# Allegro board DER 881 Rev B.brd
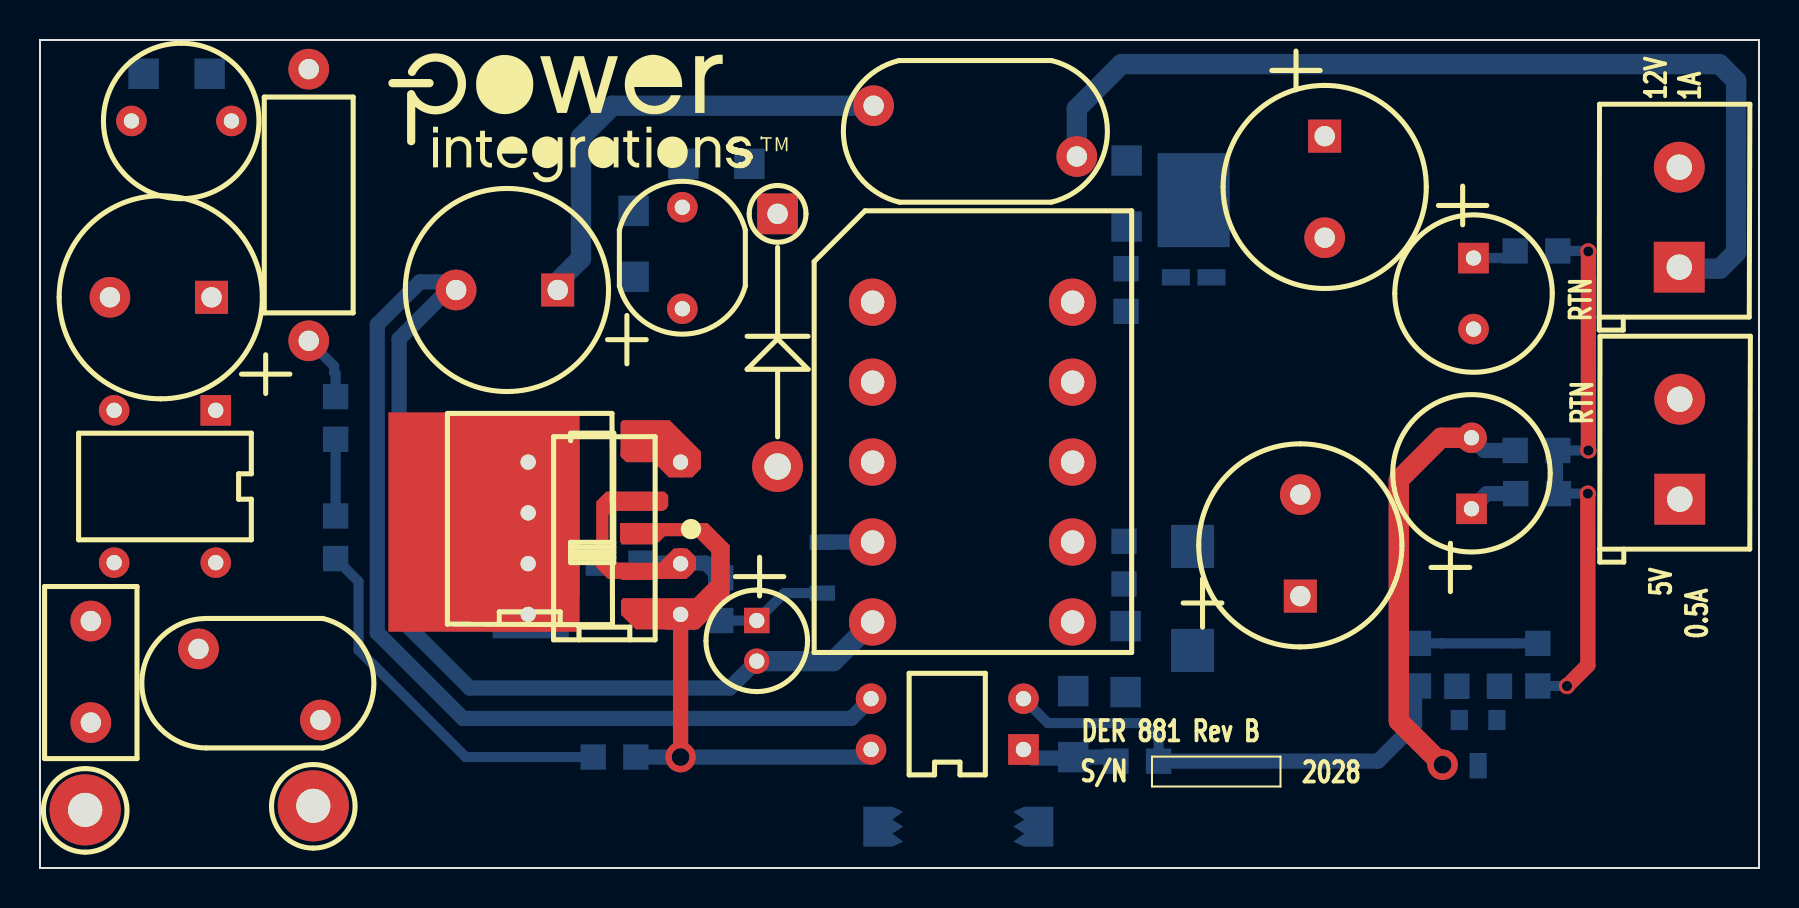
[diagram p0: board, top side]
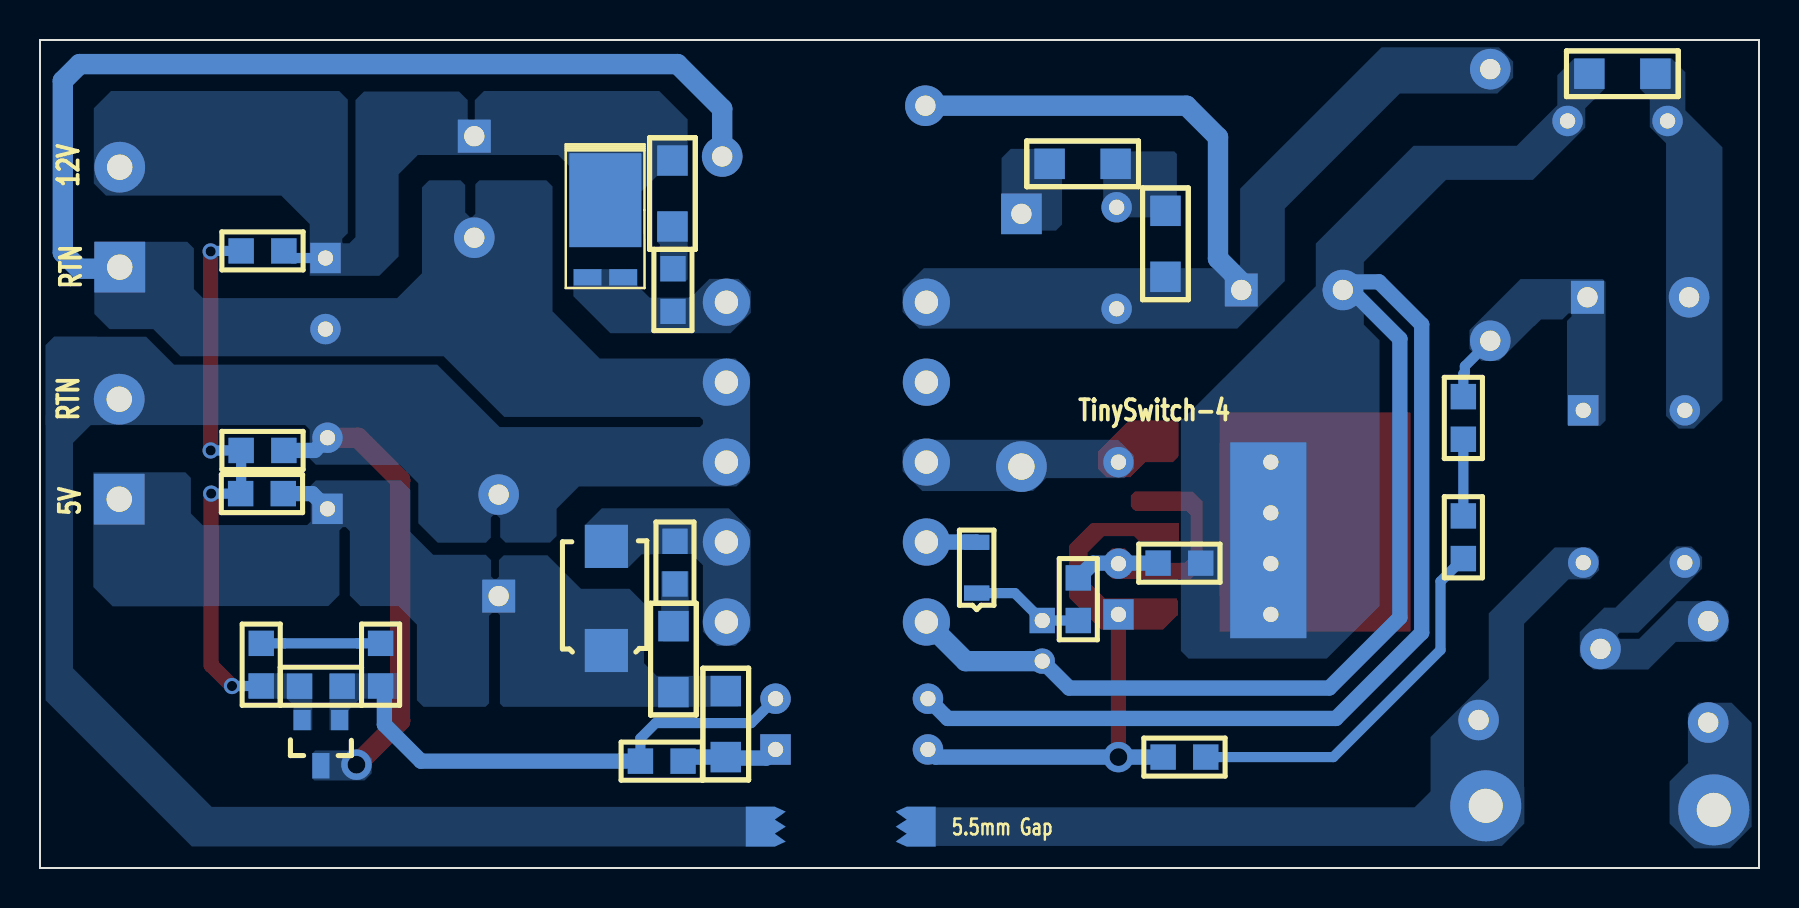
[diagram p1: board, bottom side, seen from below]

Outline 85.95 x 41.43 mm; copper layers: TOP, BOTTOM. Coordinates in mm from the lower left corner of the outline.
Outline path: 0,41.43 0,0 85.95,0 85.95,41.43 0,41.43

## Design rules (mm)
constraint set DEFAULT: min track width 0.508

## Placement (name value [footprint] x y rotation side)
BR1  DF10M  [PI_4-EDIP]  8.79 22.9 180 top
C1  18 uF  [PIPOLCAPCYLD400LS200040]  8.58 28.55 180 top
C2  18 uF  [PIPOLCAPCYLD400LS200040]  25.89 28.92 180 top
C3  1 nF  [PI_NP_CAP300X250LS200D030]  32.12 27.98 90 top
C4  0.1 uF  [PISMC0805]  30.05 15.25 180 bottom
C5  10 uF  [PIPOLCAPCLYD200LS80030]  35.84 12.38 270 top
C6  1 nF  [PINPYCAPRAD540X290LS400040]  41.68 38.14 0 top
C7  220 pF  [PISMC0805]  54.31 27.85 90 bottom
C8  1 nF  [PISMC0805]  54.2 16.35 270 bottom
C9  220 nF  [PISMC0805]  68.92 9.11 90 bottom
C10  1200 uF  [PIPOLCAPCYLD400LS200040]  63.02 13.6 90 top
C11  470  uF  [PIPOLCAPCLYD320LS140030]  71.58 17.97 90 top
C12  1000 uF  [PIPOLCAPCYLD400LS200040]  64.24 36.61 270 top
C13  680 uF  [PIPOLCAPCLYD320LS140030]  71.68 30.52 270 top
C15  1 uF  [PISMC0805]  70.84 9.09 0 bottom
D1  1N4007GP  [PIDV200X110X040DO41]  36.88 30.95 270 top
D2  BAV19WS  [PISMSOD323]  39.12 13.75 90 bottom
D3  PDS5100-13  [PISMDPOWERDI5]  58.57 29.55 180 bottom
D4  B280-13-F  [PISMSMB]  57.63 10.88 90 bottom
F1  1.25 A  [PI_RST_MICROFUSE]  2.54 7.28 90 top
J1  TERMINAL BLOCK  [PI_TERM_BLOCK_2PIN_LS200]  81.97 30.06 0 top
J2  TERMINAL BLOCK  [PI_TERM_BLOCK_2PIN_LS200]  81.99 18.45 0 top
L  WHT  [PITPKEYSTONE125X125]  2.26 2.91 0 top
L1  1000 uH  [PICHOKETOKINVD345H453LS197D030]  4.57 37.38 0 top
L2  Ferrite Bead (3.5 x 4.45 mm)  [PI12WRESD180LS675D040]  13.44 24.6 90 top
N  BLK  [PITPKEYSTONE125X125]  13.67 3.11 0 top
NOREF  -  []  -231.65 -152.08 0 top
NOREF#2  -  []  -153.83 46.93 0 top
NOREF#3  -  []  85.95 41.43 270 top
NOREF#4  -  []  0 41.43 0 top
NOREF#5  -  []  17.42 40.73 0 top
R1  1.3 M  [PISMR0805]  14.78 23.58 270 bottom
R2  1.3 M  [PISMR0805]  14.78 17.62 270 bottom
R3  1.3 M  [PISMR0805]  27.66 5.55 0 bottom
R4  332 k  [PISMR1206]  29.68 29.58 90 bottom
R5  100  [PISMR1206]  32.17 35.23 0 bottom
R6  9.1 k  [PISMR0805]  34.04 14.52 270 bottom
R8  51  [PISMR1206]  54.33 32.09 90 bottom
R9  10  [PISMR1206]  54.28 12.1 270 bottom
R10  1.00 k  [PISMR0805]  53.8 5.35 0 bottom
R11  3.30 k  [PISMR0805]  74.89 9.11 90 bottom
R12  100  [PISMR1206]  51.66 5.55 90 bottom
R13  33.2 k  [PISMR0805]  73.79 18.73 0 bottom
R14  54.9 k  [PISMR0805]  73.76 30.87 0 bottom
R15  10 k  [PISMR0805]  75.9 20.89 180 bottom
R17  10 k  [PISMR1206]  5.18 39.74 0 bottom
RV1A  300 Vac  [PIDISC350X225LS240X140040]  7.92 10.96 0 top
SG1  5.5mm gap  [PI_SPARK_GAP_5P5MM]  45.91 2.07 0 bottom
T1  EE19  [PI_BOBBIN_EE19_TF-1932_10P]  41.63 28.31 0 top
U1  TNY289PG  [PIICDIP8CSHORT5678]  32.03 12.69 90 top
U2  PS2501-1-H-A  [PI_DIP4]  49.17 5.93 90 top
U3  TL431CDBZR  [PISMSOT23123_1]  72.85 7.4 0 bottom
U4A  TNY289KG  [PI_SMD_ESOP_11-12P_SHORT7-11]  29.92 13.02 90 top
U5A  TNY288DG*  [PISMSO8DNSHORT5678]  30.21 16.93 90 top

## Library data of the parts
BR1 = DIODE BRIDGE_+-~~
C1 C2 = CAP POL: alternate symbols: (pipolcapclyd395x630ls200030h)
C3 C4 C7 C9 C15 = CAP NP
C5 = CAP POL: alternate symbols: (pipolcapclyd200ls80030h)
C6 = CAP NP: alternate symbols: (pinpycaprad540x290ls400040h,pinpycaprad500x220ls400040)
C8 = CAP NP: alternate symbols: (pismc0805_1)
C10 C12 = CAP POL: alternate symbols: (pipolcapcyld400ls200040800h)
C11 = CAP POL: alternate symbols: (pipolcapclyd320ls140030430h)
C13 = CAP POL: alternate symbols: (pipolcapclyd320ls140d30h750)
D1 = DIODE: alternate symbols: (pidax475x125040do41,pidv200x110x040do41wbead,pidax390x125040do41)
D2 = DIODE
D3 = DIODE SCHOTTKY_PWRDI_AAC
D4 = DIODE SCHOTTKY
F1 = FUSE: alternate symbols: (pirstmicrofusehoz)
J1 J2 = CON2
L N = TESTPOINT
L1 = INDUCTOR
L2 = INDUCTOR: alternate symbols: (pi12wvresd180ls150d040,pi12wvresd180ls200d040,pi12wvresd180ls250d040)
R1-R6 R8-R15 R17 = R
RV1A = VARISTOR
SG1 = SPARK_GAP
T1 = BEE19_10P/GENERIC
U1 U5A = TNY_3
U2 = OPTO_DIP
U3 = TL431CDBZR
U4A = DEV_TNY_3_eSOP

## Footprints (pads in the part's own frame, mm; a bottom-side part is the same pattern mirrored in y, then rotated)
PI12WRESD180LS675D040
  round 2.032 hole 1.016: 1(1.778,0) 2(15.367,0)
PI_4-EDIP
  rect 1.524x1.524 hole 0.762: 1(0,0)
  round 1.524 hole 0.762: 2(5.08,0) 3(5.08,7.62) 4(0,7.62)
PI_BOBBIN_EE19_TF-1932_10P
  round 2.362 hole 1.168: 1(0,0) 2(0,-4) 3(0,-8.001) 4(0,-11.999) 5(0,-16) 6(10,-16) 7(10,-11.999) 8(10,-8.001) 9(10,-4) 10(10,0)
PI_DIP4
  rect 1.524x1.524 hole 0.762: 1(0,0)
  round 1.524 hole 0.762: 2(2.54,0) 3(2.54,7.62) 4(0,7.62)
PI_NP_CAP300X250LS200D030
  round 1.524 hole 0.762: 1(0,0) 2(5.08,0)
PI_RST_MICROFUSE
  round 2.032 hole 1.016: 1(0,0) 2(5.08,0)
PI_SMD_ESOP_11-12P_SHORT7-11
  rect 0.762x1.727 smd: 1(0,0) 2(1.778,0) 3(3.556,0) 4(5.334,0) 6(8.89,0) 7(8.89,10.897) 8(7.112,10.897) 9(5.334,10.897) 10(3.556,10.897) 11(1.778,10.897) 12(0,10.897)
PI_SPARK_GAP_5P5MM
  custom 0.5x0.5 smd: 1(-3.75,0) 2(3.75,0)
PI_TERM_BLOCK_2PIN_LS200
  rect 2.54x2.54 hole 1.27: 1(0,0)
  round 2.54 hole 1.27: 2(0,5.001)
PICHOKETOKINVD345H453LS197D030
  round 1.524 hole 0.762: 1(0,0) 2(5,0)
PIDISC350X225LS240X140040
  round 2.032 hole 1.016: 1(0,0) 2(6.096,-3.556)
PIDV200X110X040DO41
  rect 2.032x2.032 hole 1.016: 1(-1.778,0)
  round 2.54 hole 1.321: 2(10.865,0)
PIICDIP8CSHORT5678
  rect 1.524x1.524 hole 0.762: 1(0,0)
  round 1.524 hole 0.762: 2(2.54,0) 4(7.62,0) 5(7.62,7.62) 6(5.08,7.62) 7(2.54,7.62) 8(0,7.62)
PINPYCAPRAD540X290LS400040
  round 2.032 hole 1.016: 1(0,0) 2(10.16,-2.54)
PIPOLCAPCLYD200LS80030
  rect 1.27x1.27 hole 0.762: 1(0,0)
  round 1.27 hole 0.762: 2(2.032,0)
PIPOLCAPCLYD320LS140030
  rect 1.524x1.524 hole 0.762: 1(0,0)
  round 1.524 hole 0.762: 2(3.556,0)
PIPOLCAPCYLD400LS200040
  rect 1.651x1.651 hole 1.016: 1(0,0)
  round 2.032 hole 1.016: 2(5.08,0)
PISMC0805
  rect 1.27x1.27 smd: 1(0,0) 2(2.134,0)
PISMDPOWERDI5
  rect 1.397x0.813 smd: 1(0,0) 3(1.778,0)
  rect 3.607x4.699 smd: 2(0.889,3.861)
PISMR0805
  rect 1.27x1.27 smd: 1(0,0) 2(2.134,0)
PISMR1206
  rect 1.524x1.524 smd: 1(0,0) 2(3.302,0)
PISMSMB
  rect 2.159x2.159 smd: 1(0,0) 2(5.207,0)
PISMSO8DNSHORT5678
  rect 0.635x2.388 smd: 1(0,0)
  oval 0.635x2.388 smd: 2(1.27,0) 4(3.81,0) 5(3.81,4.978) 6(2.54,4.978) 7(1.27,4.978) 8(0,4.978)
PISMSOD323
  rect 0.762x1.27 smd: 1(0,0) 2(2.54,0)
PISMSOT23123_1
  rect 0.864x1.016 smd: 1(-1.88,0) 2(0,0)
  rect 0.864x1.27 smd: 3(-0.94,2.286)
PITPKEYSTONE125X125
  round 3.556 hole 1.702: 1(0,0)

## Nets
BP: C4.1 R6.1 U1.2 U4A.2 U5A.2
D: D1.2 T1.3 U1.4 U4A.6 U5A.4
EN: R3.2 U1.1 U2.4 U4A.1 U5A.1
NC3: U4A.3
NC4: U4A.4
S: C2.2 C4.2 C5.2 L1.2 R17.2 T1.5 U1.5(S) U2.3(E) U4A.7(S7) U5A.5(S)
SOURCE: U1.6 U1.7 U1.8 U4A.8 U4A.9 U4A.10 U4A.11 U4A.12 U5A.6 U5A.7 U5A.8
N12047772: F1.1 L.1
N12047776: BR1.3 F1.2 RV1A.1
N12047800: C2.1 C3.1 C6.1 L2.2 R4.1 T1.1
N12047808: C6.2 C10.2 C11.2 C12.2 C13.2 J1.1 J2.2 R15.2 SG1.2 T1.8 T1.9 U3.3
N12047874: C7.1 D3.1 D3.3 T1.10
N12047882: C7.2 R8.1
N12047886: C12.1 C13.1 D3.2 J1.2 R8.2 R14.1
N12047956: BR1.2 C1.2 L1.1 R17.1
N12047964: BR1.1 C1.1 L2.1 R1.1
N12048106: BR1.4 N.1 RV1A.2 SG1.1
N12048278: R1.2 R2.1
N12048330: C3.2 R4.2 R5.1
N12048338: D1.1 R5.2
N12048416: D2.2 T1.4
N12048424: C8.1 D4.2 T1.6 T1.7
N12048440: C10.1 C11.1 D4.1 J2.1 R9.2 R12.2 R13.1
N12048540: R2.2 R3.1
N12048564: C8.2 R9.1
N12048682: C5.1 D2.1 R6.2
N12048994: R10.1 R12.1 U2.1
N12049130: C9.1 C15.1 R10.2 U2.2 U3.1
N12049134: C15.2 R11.1 R13.2 R14.2 R15.1 U3.2(VREF)
N12051927: C9.2 R11.2

Pads without a net: T1 2

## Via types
v1: diameter 0.813, hole 0.508, TOP to BOTTOM, 4 vias
v2: diameter 1.524, hole 0.889, TOP to BOTTOM, 2 vias

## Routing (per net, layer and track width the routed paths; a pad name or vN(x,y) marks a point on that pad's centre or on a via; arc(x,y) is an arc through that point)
BP: length 4.3
  BOTTOM w0.762: R6.1 33.3,15.25 32.05,15.25 U1.2 32,15.25 C4.1
EN: length 19.1
  TOP w0.762: U1.1 v2(32.03,5.55)
  BOTTOM w0.762: U2.4 41.17,5.55 v2(32.03,5.55) R3.2
S: length 91.6
  BOTTOM w0.762: U2.3 40.57,7.48 21.16,7.48 16.87,11.77 16.87,27.19 19,29.33 20.81,29.33 17.96,26.48 17.96,12.54 21.49,9 34.49,9 C5.2
  BOTTOM w1.016: T1.5 39.67,10.35 C5.2
N12047800: length 23
  BOTTOM w1.016: C6.1 28.63,38.14 27.05,36.56 27.05,30.49 25.89,29.33
N12047808: length 70.5
  TOP w1.016: C11.2 70.05,21.53 67.94,19.42 67.94,7.35 v2(70.13,5.17)
  BOTTOM w0.762: C11.2 72.21,20.89 R15.2
  BOTTOM w1.016: C6.2 51.84,37.99 54.08,40.22 83.97,40.22 84.81,39.38 84.81,30.8 84,29.99 82.04,29.99 J1.1
N12047886: length 2.2
  BOTTOM w0.508: C13.1 73.41,30.52 R14.1
N12047964: length 3.4
  BOTTOM w0.508: R1.1 14.78,24.73 14.71,24.8 14.71,25.11 L2.1
N12048278: length 3.8
  BOTTOM w0.508: R1.2 R2.1
N12048416: length 2.5
  BOTTOM w0.762: D2.2 39.13,16.31 T1.4
N12048440: length 2.5
  BOTTOM w0.762: R13.1 72.34,18.73 C11.1
N12048540: length 19
  BOTTOM w0.508: R3.1 21.29,5.55 15.93,10.91 15.93,14.34 R2.2
N12048682: length 5.6
  BOTTOM w0.508: R6.2 C5.1 37.21,13.75 D2.1
N12048994: length 4.9
  BOTTOM w0.762: U2.1 49.2,5.93 49.63,5.5 51.61,5.5 R12.1 53.59,5.55 R10.1
N12049130: length 24.2
  BOTTOM w0.508: U2.2 50.39,7.25 55.17,7.25 55.93,6.49 R10.2
  BOTTOM w0.762: R10.2 66.9,5.35 68.73,7.18 68.73,9.11
N12049134: length 28.2
  TOP w0.762: v1(77.39,18.73) 77.39,10.15 v1(76.35,9.11) ; v1(77.42,30.85) v1(77.42,20.89)
  BOTTOM w0.508: v1(77.39,18.73) R13.2 75.9,18.76 R15.1 v1(77.42,20.89) ; v1(77.42,30.85) 77.39,30.87 R14.2 ; 74.9,9.11 v1(76.35,9.11)
N12051927: length 6
  BOTTOM w0.508: C9.2 70.07,11.24 R11.2

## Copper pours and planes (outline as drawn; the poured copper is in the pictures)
BP on TOP (solid shape): 31.41,18.64 31.41,18.1 31.18,17.87 28.63,17.87 28.42,17.67 28.42,15.56 28.7,15.28 30.99,15.28 31.7,15.99 32.36,15.99 32.8,15.55 32.8,14.95 32.32,14.47 28.4,14.47 27.81,15.05 27.81,18.33 28.32,18.83 31.22,18.83
D on TOP (solid shape): 33.05,20.84 33.05,19.98 32.61,19.55 31.45,19.55 30.68,20.31 29.31,20.31 29.03,20.59 29.03,22.29 29.15,22.4 31.48,22.4
D on BOTTOM: 42.82,19.85 42.82,20.89 42.29,21.43 32.05,21.43 31.27,20.64 31.27,19.98 31.74,19.51 35.65,19.51 36.3,18.86 41.83,18.86
EN on TOP (solid shape): 34.49,16.14 34.49,13.53 32.91,11.94 29.78,11.94 29.11,12.61 29.11,13.5 32.72,13.5 33.57,14.35 33.57,15.8 32.77,16.6 31.24,16.6 30.94,16.29 29.01,16.29 29.01,17.26 33.38,17.26
S on TOP (solid shape): 26.97,11.82 17.42,11.82 17.42,22.8 26.97,22.8
S on BOTTOM (solid shape): 26.44,11.49 22.63,11.49 22.63,21.3 26.44,21.3
S on BOTTOM: 21.62,10.48 18.97,13.12 18.97,26.4 19.76,27.19 19.76,30.32 15.65,34.43 11.3,34.43 8.69,37.05 8.69,38.01 7.72,38.98 7.72,40.5 9.25,40.5 10.08,39.66 10.08,38.16 12.12,36.13 17.27,36.13 22.16,31.24 22.16,29.11 28.8,22.47 28.91,22.47 28.91,10.86 28.52,10.48
SOURCE on TOP (solid shape): 26.81,16.4 23.51,16.4 23.51,21.22 26.81,21.22
SOURCE on TOP (solid shape): 22.12,14.42 18.16,14.42 18.16,22.29 22.12,22.29
SOURCE on TOP (solid shape): 26.97,13.65 21.95,13.65 21.95,21.25 26.97,21.25
N12047772 on BOTTOM: 3.53,5.27 3.56,5.3 3.56,7.73 3.02,8.27 1.37,8.27 0.37,7.26 0.37,2.07 1.45,0.98 3.23,0.98 4.47,2.23 4.47,4.33
N12047776 on BOTTOM: 2.11,11.32 4.15,11.32 5.54,9.93 8.29,9.93 8.97,10.61 8.97,11.8 7.73,13.03 7.18,13.03 4.11,16.09 3.38,16.09 2.84,15.56 2.84,14.97 6.05,11.77 6.96,11.77 7.06,11.67 7.06,11.57 6.96,11.47 5.99,11.47 4.11,13.35 2.03,13.35 1.52,12.84 1.52,11.9
N12047800 on BOTTOM: 42.82,28.94 42.82,27.83 41.99,26.99 26.09,26.99 23.71,29.36 23.71,33 17.96,38.75 13.08,38.75 12.29,39.54 12.29,40.35 13,41.06 18.87,41.06 25.95,33.99 25.95,30.2 26.14,30.01 41.76,30.01
N12047808 on BOTTOM: 72.16,20.18 67.97,20.18 67.04,19.25 67.04,17.25 66.07,16.28 63.66,16.28 63.41,16.52 63.41,17.53 63.27,17.67 63.12,17.67 62.94,17.49 62.94,16.55 62.67,16.28 60.45,16.28 60.12,16.61 60.12,17.97 59,19.09 51.13,19.09 50.44,19.77 50.44,24.75 51.18,25.49 57.96,25.49 60.32,27.85 60.32,34.1 60.63,34.4 63.98,34.4 64.19,34.2 64.19,32.73 64.34,32.58 64.47,32.58 64.69,32.8 64.69,34.18 64.92,34.4 66.5,34.4 66.85,34.05 66.85,29.76 68.1,28.51 77.8,28.51 78.26,28.97 78.26,31 78.59,31.33 83.21,31.33 83.21,30.14 83.24,30.11 83.24,27.72 82.47,26.96 80.29,26.96 78.93,25.6 65.77,25.6 62.74,22.57 52.96,22.57 52.81,22.42 52.81,22.21 52.96,22.06 62.97,22.06 66.09,25.18 79.25,25.18 80.64,26.58 85.24,26.58 85.66,26.16 85.66,22.66 85.67,22.64 85.67,22.16 72.69,22.16 72.47,21.93 72.47,20.49
N12047808 on BOTTOM: 72.19,5.88 72.34,5.73 72.34,4.48 72.24,4.38 69.72,4.38 69.37,4.74 69.37,5.47 69.77,5.88
N12047808 on BOTTOM: 85.24,26.58 83.11,26.58 82.83,26.3 82.83,22.16 83.41,22.16 84.3,21.27 84.3,10 77.37,3.06 49.63,3.06 49.63,1.08 78.36,1.08 85.67,8.4 85.67,26.15
N12047874 on BOTTOM: 51.42,26.76 57.44,26.76 59.28,28.61 59.28,29.96 56.08,29.96 56.08,29.15 55.47,28.54 53.42,28.54 52.48,29.48 51.03,29.48 50.41,28.85 50.41,27.78
N12047882 on BOTTOM: 53.67,29.35 54.94,29.35 54.95,29.36 54.95,31.19 55.09,31.33 55.09,32.86 53.57,32.86 53.57,29.45
N12047886 on BOTTOM: 67.08,35.67 60.05,35.67 59.49,35.12 59.49,31.06 55.88,31.06 55.88,33.85 55.09,34.63 53.57,34.63 53.57,37.45 54.99,38.88 63.75,38.88 64.21,38.42 64.21,37.45 64.31,37.35 64.41,37.35 64.57,37.5 64.57,38.42 65,38.85 69.75,38.85 70.18,38.42 70.18,31.56 70.48,31.26 70.79,31.26 70.84,31.31 70.84,31.48 70.56,31.76 70.56,38.44 70.99,38.88 82.4,38.88 83.26,38.01 83.26,34.25 82.65,33.64 73.89,33.64 72.47,32.22 72.47,29.63 68.99,29.63 68.02,30.59 68.02,34.71 67.08,35.65
N12047956 on BOTTOM: 3.25,21.98 1.83,23.41 1.83,36.06 3.68,37.91 3.68,39.82 4.39,40.53 5.94,40.53 5.94,38.98 5.46,38.49 5.46,37.07 4.65,36.26 4.65,22.62 4.01,21.98
N12047964 on BOTTOM: 7.67,22.39 7.67,29.32 7.81,29.46 11.93,29.46 14.48,26.91 14.48,25.97 13.88,25.38 12.99,25.38 11.25,27.12 11.23,27.12 10.9,27.45 9.83,27.45 9.53,27.75 9.42,27.75 9.37,27.7 9.37,27.6 9.6,27.37 9.6,22.19 9.53,22.11 7.95,22.11
N12048106 on BOTTOM: 42.19,3.04 42.19,1.11 12.85,1.11 11.73,2.22 11.73,4.05 12.47,4.79 15.47,4.79 17.22,3.04
N12048106 on BOTTOM: 11.75,12.22 9.53,14.44 8.46,14.44 8,14.9 8,15.58 8.46,16.04 10.21,16.04 13.51,12.74 13.51,9.46 16.42,6.55 16.42,1.96 15.65,1.18 12.88,1.18 11.75,2.31
N12048330 on BOTTOM: 29.11,32.55 32.46,32.55 32.79,32.88 32.79,35.85 29.24,35.85 29.11,35.73
N12048338 on BOTTOM: 37.87,35.52 37.41,35.98 35.03,35.98 34.85,35.8 34.85,32.2 35.15,31.89 37.69,31.89 37.87,32.07
N12048424 on BOTTOM: 53.37,15.71 55.17,15.71 55.18,15.7 55.87,15.7 56.54,15.02 58.7,15.02 58.7,17.16 57.86,18 51.51,18 50.42,16.9 50.42,11.88 51.18,11.11 52.1,11.11 52.81,11.82 52.81,15.15
N12048440 on BOTTOM: 56.48,13.97 55.75,13.25 55.75,10.25 55.12,9.61 50.9,9.61 50.9,8.22 51.05,8.07 62.79,8.07 62.95,8.23 62.95,12.65 63.09,12.79 63.32,12.79 63.5,12.61 63.5,8.24 63.68,8.07 66.78,8.07 67.11,8.4 67.11,12.18 68.03,13.11 69.94,13.11 70.46,13.63 70.46,16.85 70.66,17.06 70.82,17.06 70.98,16.89 70.98,13.67 71.54,13.11 77.08,13.11 77.09,13.09 82.32,13.09 83.29,14.06 83.29,19.8 78.69,19.8 78.41,19.52 78.41,17.74 77.83,17.16 72.59,17.16 72.42,17.34 72.42,19.14 72.16,19.39 67.92,19.39 67.44,18.91 67.44,16.82 66.29,15.67 63.67,15.67 63.4,15.41 63.4,14.59 63.27,14.47 63.12,14.47 63,14.58 63,15.41 62.76,15.65 60.58,15.65 58.9,13.97
N12048564 on BOTTOM: 53.52,11.34 54.84,11.34 54.89,11.39 54.89,14.85 53.52,14.85
N12049130 on BOTTOM: 71.48,6.9 71.48,9.74 68.02,9.74 68.02,8.47 69.95,8.47 70.54,7.89 70.54,6.9
N12049134 on BOTTOM: 72.34,6.92 72.36,6.9 73.28,6.9 73.28,8.14 73.61,8.47 75.49,8.47 75.54,8.52 75.54,9.74 72.34,9.74

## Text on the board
Ref Des/Silkscreen Bottom: TinySwitch-4 | RTN | 5V | 12V
Ref Des/Silkscreen Top: S/N | DER 881 Rev B | 2028 | RTN | 12V | 5V | 1A | 0.5A
User.6: 14.  FAB HOUSE LOGO,DATE CODE TO BE IN SILK SCREEN ONLY.DO NOT USE COPPER. | 13.  MATERIAL FR4 COPPER 2oz THICKNESS 0.062"
User.8: FIGURE | FINISHED_SIZE | 20.0 | 30.0 | 35.0 | 40.0 | 46.0 | 50.0 | 52.0 | 67.0 | DRILL CHART: TOP to BOTTOM | ALL UNITS ARE IN MILS | TOLERANCE_DRILL | +0.0/-0.0 | +3.0/-3.0 | PLATED | QTY | 4 | 23 | 2 | 17 | 10 | 1
